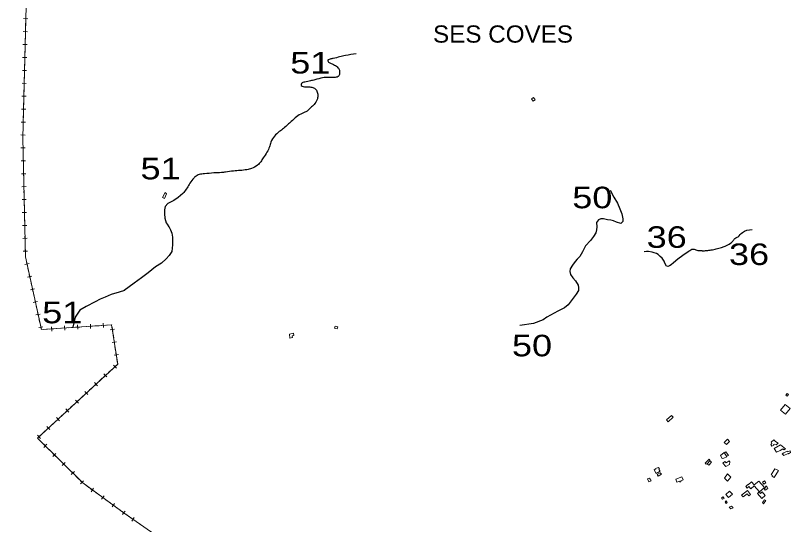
# Model space of a CAD drawing. Extents: x 476989 to 498418, y 4381813 to 4416555.
# Drawn here: x 483851 to 485648, y 4385368 to 4386550 of the extents above; entities that cross this region are included whole.
import ezdxf
from ezdxf.enums import TextEntityAlignment as Align

# ---------------------------------------------------------------- set-up
doc = ezdxf.new("R2010")
doc.units = 0
doc.header["$LTSCALE"] = 20
doc.linetypes.add('MEDIUM_DASHED', pattern=[4.5, 3, -1.5])
for name, color, linetype, lineweight in [('13', 7, 'Continuous', 13), ('34', 7, 'Continuous', 13), ('47', 7, 'Continuous', 13), ('48', 7, 'MEDIUM_DASHED', 13), ('6', 7, 'Continuous', 25)]:
    doc.layers.add(name, color=color, linetype=linetype, lineweight=lineweight)
doc.layers.add('7', color=7, linetype='Continuous')

msp = doc.modelspace()

# ---------------------------------------------------------------- linework, layer by layer
at = {"layer": '34'}
for p, q in [((483869.82, 4386542.81), (483879.82, 4386542.56)), ((483874.94, 4386547.69), (483874.7, 4386537.69)), ((483874.57, 4386532.69), (483874.33, 4386522.69)), ((483869.08, 4386512.82), (483879.08, 4386512.57)), ((483873.83, 4386502.7), (483873.59, 4386492.7)), ((483874.2, 4386517.7), (483873.96, 4386507.7)), ((483868.34, 4386482.83), (483878.34, 4386482.58)), ((483873.46, 4386487.7), (483873.22, 4386477.71)), ((483873.09, 4386472.71), (483872.85, 4386462.71)), ((483867.6, 4386452.84), (483877.6, 4386452.59)), ((483872.5, 4386448.65), (483872.48, 4386447.72)), ((483872.72, 4386457.71), (483872.5, 4386448.65)), ((483872.35, 4386442.72), (483872.11, 4386432.72)), ((483866.86, 4386422.85), (483876.86, 4386422.6)), ((483871.62, 4386412.73), (483871.37, 4386402.73)), ((483871.99, 4386427.72), (483871.74, 4386417.73)), ((483866.12, 4386392.86), (483876.12, 4386392.61)), ((483871.25, 4386397.73), (483871, 4386387.74)), ((483870.88, 4386382.74), (483870.63, 4386372.74)), ((483865.39, 4386362.87), (483875.38, 4386362.62)), ((483870.51, 4386367.74), (483870.26, 4386357.74)), ((483870.14, 4386352.75), (483869.89, 4386342.75)), ((483864.65, 4386332.88), (483874.64, 4386332.63)), ((483869.4, 4386322.75), (483869.15, 4386312.76)), ((483869.77, 4386337.75), (483869.52, 4386327.75)), ((483869.03, 4386307.76), (483868.78, 4386297.76)), ((483863.91, 4386302.88), (483873.9, 4386302.64)), ((483868.66, 4386292.76), (483868.41, 4386282.77)), ((483863.17, 4386272.89), (483873.17, 4386272.65)), ((483868.29, 4386277.77), (483868.04, 4386267.77)), ((483868.07, 4386262.77), (483868.29, 4386252.78)), ((483863.51, 4386242.67), (483873.5, 4386242.89)), ((483868.4, 4386247.78), (483868.61, 4386237.78)), ((483868.72, 4386232.78), (483868.94, 4386222.78)), ((483869.05, 4386217.78), (483869.27, 4386207.79)), ((483864.16, 4386212.68), (483874.16, 4386212.89)), ((483869.37, 4386202.79), (483869.59, 4386192.79)), ((483864.81, 4386182.68), (483874.81, 4386182.9)), ((483869.7, 4386187.79), (483869.92, 4386177.79)), ((483870.03, 4386172.79), (483870.24, 4386162.8)), ((483865.46, 4386152.69), (483875.46, 4386152.91)), ((483870.35, 4386157.8), (483870.57, 4386147.8)), ((483870.68, 4386142.8), (483870.9, 4386132.8)), ((483871, 4386127.8), (483871.22, 4386117.81)), ((483866.11, 4386122.7), (483876.11, 4386122.91)), ((483871.33, 4386112.81), (483871.55, 4386102.81)), ((483866.77, 4386092.7), (483876.76, 4386092.92)), ((483871.66, 4386097.81), (483871.87, 4386087.81)), ((483871.98, 4386082.82), (483872.2, 4386072.82)), ((483867.42, 4386062.71), (483877.42, 4386062.93)), ((483872.31, 4386067.82), (483872.53, 4386057.82)), ((483872.63, 4386052.82), (483872.85, 4386042.82)), ((483872.96, 4386037.83), (483873.18, 4386027.83)), ((483868.07, 4386032.72), (483878.07, 4386032.94)), ((483873.29, 4386022.83), (483873.5, 4386012.83)), ((483868.72, 4386002.73), (483878.72, 4386002.94)), ((483873.61, 4386007.83), (483873.83, 4385997.84)), ((483872.79, 4385972.17), (483882.55, 4385974.3)), ((483876.6, 4385978.12), (483878.74, 4385968.35)), ((483879.81, 4385963.47), (483881.95, 4385953.7)), ((483879.2, 4385942.86), (483888.97, 4385945)), ((483883.02, 4385948.81), (483885.16, 4385939.04)), ((483886.23, 4385934.16), (483888.36, 4385924.39)), ((483885.62, 4385913.55), (483895.39, 4385915.69)), ((483889.43, 4385919.51), (483891.57, 4385909.74)), ((483892.64, 4385904.85), (483894.78, 4385895.09)), ((483895.85, 4385890.2), (483897.99, 4385880.43)), ((483892.03, 4385884.25), (483901.8, 4385886.39)), ((483899.06, 4385875.55), (483901.2, 4385865.78)), ((483898.45, 4385854.94), (483908.22, 4385857.08)), ((483902.27, 4385860.9), (483904.4, 4385851.13)), ((483905.47, 4385846.24), (483907.61, 4385836.47)), ((484055.17, 4385825.72), (484054.5, 4385835.7)), ((483904.87, 4385825.64), (483914.64, 4385827.77)), ((483908.68, 4385831.59), (483910.82, 4385821.82)), ((483915.15, 4385821.28), (483925.13, 4385821.95)), ((483930.12, 4385822.29), (483940.09, 4385822.96)), ((483935.44, 4385817.64), (483934.77, 4385827.62)), ((483945.08, 4385823.3), (483955.06, 4385823.97)), ((483960.05, 4385824.31), (483970.03, 4385824.98)), ((483965.37, 4385819.66), (483964.7, 4385829.64)), ((483975.01, 4385825.32), (483984.99, 4385825.99)), ((483989.98, 4385826.33), (483999.96, 4385827)), ((483995.31, 4385821.68), (483994.63, 4385831.66)), ((484004.95, 4385827.34), (484014.92, 4385828.01)), ((484019.91, 4385828.35), (484029.89, 4385829.02)), ((484025.24, 4385823.7), (484024.56, 4385833.68)), ((484034.88, 4385829.36), (484044.86, 4385830.03)), ((484049.84, 4385830.37), (484059.82, 4385831.04)), ((484070.7, 4385820.58), (484080.58, 4385822.1)), ((484074.88, 4385826.28), (484076.4, 4385816.39)), ((484077.16, 4385811.45), (484078.68, 4385801.57)), ((484075.26, 4385790.93), (484085.14, 4385792.45)), ((484079.44, 4385796.63), (484080.96, 4385786.74)), ((484081.72, 4385781.8), (484083.24, 4385771.92)), ((484084, 4385766.98), (484085.52, 4385757.09)), ((484079.82, 4385761.27), (484089.71, 4385762.79)), ((484086.28, 4385752.15), (484087.81, 4385742.27)), ((484074.26, 4385728.29), (484066.92, 4385721.5)), ((484085.27, 4385738.48), (484077.93, 4385731.69)), ((484078.2, 4385738.75), (484084.99, 4385731.41)), ((484063.24, 4385718.11), (484055.9, 4385711.32)), ((484056.18, 4385718.38), (484062.97, 4385711.04)), ((484041.22, 4385697.74), (484033.88, 4385690.95)), ((484034.15, 4385698.02), (484040.94, 4385690.67)), ((484052.23, 4385707.92), (484044.89, 4385701.13)), ((484019.19, 4385677.37), (484011.85, 4385670.58)), ((484012.13, 4385677.65), (484018.92, 4385670.31)), ((484030.21, 4385687.56), (484022.86, 4385680.77)), ((483997.17, 4385657), (483989.82, 4385650.21)), ((483990.1, 4385657.28), (483996.89, 4385649.94)), ((484008.18, 4385667.19), (484000.84, 4385660.4)), ((483986.15, 4385646.82), (483978.81, 4385640.03)), ((483964.13, 4385626.45), (483956.79, 4385619.66)), ((483975.14, 4385636.64), (483967.8, 4385629.85)), ((483968.07, 4385636.91), (483974.86, 4385629.57)), ((483942.1, 4385606.08), (483934.76, 4385599.29)), ((483953.11, 4385616.27), (483945.77, 4385609.48)), ((483946.05, 4385616.54), (483952.84, 4385609.2)), ((483920.08, 4385585.71), (483912.73, 4385578.93)), ((483931.09, 4385595.9), (483923.75, 4385589.11)), ((483924.02, 4385596.18), (483930.81, 4385588.83)), ((483902, 4385575.81), (483908.79, 4385568.47)), ((483905.82, 4385565.21), (483912.93, 4385558.18)), ((483916.48, 4385554.66), (483923.58, 4385547.62)), ((483916.51, 4385547.59), (483923.55, 4385554.69)), ((483927.14, 4385544.1), (483934.24, 4385537.06)), ((483937.79, 4385533.55), (483944.9, 4385526.51)), ((483937.83, 4385526.48), (483944.87, 4385533.58)), ((483948.45, 4385522.99), (483955.56, 4385515.95)), ((483959.11, 4385512.43), (483966.21, 4385505.4)), ((483959.14, 4385505.36), (483966.18, 4385512.47)), ((483969.77, 4385501.88), (483976.87, 4385494.84)), ((483980.42, 4385491.32), (483987.53, 4385484.29)), ((483980.46, 4385484.25), (483987.49, 4385491.36)), ((483991.08, 4385480.77), (483998.19, 4385473.73)), ((484001.77, 4385463.14), (484008.81, 4385470.25)), ((484013.14, 4385460.53), (484021.22, 4385454.63)), ((484025.26, 4385451.69), (484033.34, 4385445.8)), ((484026.35, 4385444.7), (484032.24, 4385452.78)), ((484037.38, 4385442.85), (484045.46, 4385436.96)), ((484049.5, 4385434.01), (484057.58, 4385428.12)), ((484050.59, 4385427.03), (484056.48, 4385435.11)), ((484061.62, 4385425.18), (484069.7, 4385419.28)), ((484073.74, 4385416.34), (484081.82, 4385410.45)), ((484074.83, 4385409.35), (484080.72, 4385417.43)), ((484085.86, 4385407.5), (484093.94, 4385401.61)), ((484097.98, 4385398.66), (484103, 4385395)), ((484099.07, 4385391.68), (484103.23, 4385397.38)), ((484103.23, 4385397.38), (484104.96, 4385399.76)), ((484107.1, 4385392.14), (484115.31, 4385386.42)), ((484119.41, 4385383.57), (484127.61, 4385377.85)), ((484120.65, 4385376.61), (484126.37, 4385384.81)), ((484131.72, 4385374.99), (484139.92, 4385369.27))]:
    msp.add_line(p, q, dxfattribs=at)
for points in [[(484108, 4387807), (483853, 4387811), (483851, 4387468), (483887, 4387037), (483872.5, 4386448.65)], [(483872.5, 4386448.65), (483868, 4386266), (483874, 4385990), (483911, 4385821), (484074, 4385832), (484088, 4385741), (483902, 4385569), (484007, 4385465), (484103, 4385395), (484103.22, 4385394.84)], [(483873.94, 4385992.84), (483874, 4385990), (483875.53, 4385983)], [(484064.81, 4385831.38), (484074, 4385832), (484074.12, 4385831.22)], [(483909.06, 4385575.53), (483902, 4385569), (483902.27, 4385568.73)], [(484001.74, 4385470.21), (484007, 4385465), (484009.1, 4385463.47)], [(484103.22, 4385394.84), (484291, 4385264), (484102.72, 4385164.38)]]:
    msp.add_lwpolyline(points, dxfattribs=at)
at = {"layer": '47'}
for points in [[(485640.17, 4385672.6), (485643.66, 4385670.19), (485640.91, 4385666.22), (485637.42, 4385668.63)], [(485635.68, 4385647.23), (485647.33, 4385637.86), (485636.56, 4385624.48), (485624.91, 4385633.85)], [(485375.86, 4385617.36), (485364.42, 4385607.2), (485360.77, 4385611.28), (485372.16, 4385621.45)], [(485501.94, 4385566.31), (485494.71, 4385558.99), (485499.66, 4385554.11), (485506.89, 4385561.43)], [(485619.69, 4385557.64), (485613.67, 4385561.55), (485609.59, 4385565.06), (485603.44, 4385559.82), (485605.27, 4385556.65), (485602.46, 4385554.21), (485604.95, 4385550.05), (485609.94, 4385552.83), (485608.92, 4385554.42), (485611.48, 4385555.06), (485615.13, 4385553.2)], [(485625.19, 4385553.51), (485610.05, 4385544.72), (485615.41, 4385536.24), (485624.62, 4385540.46), (485630.23, 4385543.98), (485632.89, 4385541.54), (485636.84, 4385544.49)], [(485500.76, 4385525.8), (485493.57, 4385522.16), (485490.11, 4385521.53), (485485.71, 4385528.5), (485494.07, 4385535.43)], [(485647.5, 4385539.76), (485641.24, 4385537.45), (485640.36, 4385539.11), (485632.5, 4385534.95), (485628.57, 4385532.83), (485632.55, 4385528.34), (485642.83, 4385533.52), (485643.57, 4385532.76), (485648.26, 4385535.32)], [(485461.45, 4385516.54), (485454.91, 4385509.66), (485458.68, 4385506.07), (485465.22, 4385512.95)], [(485491.39, 4385511.08), (485498.17, 4385502.8), (485506.43, 4385508.01), (485507.49, 4385514.15), (485506.17, 4385515.97), (485499.43, 4385512.02), (485496.02, 4385514.62)], [(485336.5, 4385486.96), (485331.77, 4385495.38), (485335.76, 4385497.44), (485335.29, 4385498.25), (485342.2, 4385500.73), (485344.58, 4385496.66), (485343.21, 4385496.15), (485345.76, 4385492.09)], [(485620.73, 4385493.69), (485610.59, 4385477.56), (485605.81, 4385480.55), (485606.79, 4385482.13), (485603.55, 4385484.13), (485612.08, 4385497.96)], [(485346.38, 4385488.49), (485348.86, 4385485.12), (485341.52, 4385480.52), (485338.96, 4385484.25)], [(485382.2, 4385473.84), (485385, 4385466.76), (485390.55, 4385468.79), (485391.34, 4385466.68), (485394.27, 4385468.09), (485393.65, 4385469.76), (485399.3, 4385472.35), (485396.43, 4385479.26)], [(485501.99, 4385486.17), (485494.94, 4385476.06), (485501.89, 4385468.84), (485509.91, 4385478.63)], [(485316.66, 4385474.25), (485319.79, 4385467.3), (485324.91, 4385469.72), (485321.65, 4385475.92)], [(485576.12, 4385444.28), (485564.24, 4385457.89), (485556.57, 4385451.2), (485551.89, 4385456.56), (485547.94, 4385453.11), (485544.46, 4385457.09), (485549.66, 4385461.64), (485550.29, 4385460.91), (485558.02, 4385467.59), (485564.31, 4385460.3), (485574.72, 4385469.29), (485587.69, 4385454.27)], [(485583.19, 4385466.47), (485586.58, 4385462.08), (485591.06, 4385465.53), (485587.67, 4385469.92)], [(485513.39, 4385438.88), (485504.37, 4385430.87), (485498, 4385438.05), (485507.02, 4385446.06)], [(485534.82, 4385436.85), (485548.41, 4385447.53), (485555.55, 4385438.42), (485551.49, 4385435.24), (485547.76, 4385439.99), (485538.35, 4385432.6)], [(485571.57, 4385440.75), (485581.68, 4385428.75), (485589.75, 4385435.55), (485582.63, 4385443.99), (485578.45, 4385440.47), (485575.5, 4385443.96)], [(485591.25, 4385458.17), (485589.16, 4385453.18), (485586.96, 4385451.48), (485589.53, 4385448.14), (485595.75, 4385452.26), (485594.06, 4385455.21)], [(485488.51, 4385430.38), (485490.9, 4385426.94), (485494.12, 4385429.18), (485491.73, 4385432.62)], [(485496.41, 4385421.49), (485499.18, 4385417.58), (485501.63, 4385419.31), (485498.86, 4385423.22)], [(485587.94, 4385426.11), (485583.51, 4385419.27), (485585.96, 4385416.4), (485590.99, 4385424.11)], [(485515.18, 4385406.96), (485509.98, 4385405.16), (485506.28, 4385408.67), (485511.49, 4385410.99)]]:
    msp.add_lwpolyline(points, close=True, dxfattribs=at)
at = {"layer": '48'}
for points in [[(485047.97, 4386357.07), (485051.39, 4386351.42), (485055.76, 4386354.03), (485052.03, 4386360.03)], [(484201.31, 4386136.21), (484196.74, 4386125.7), (484192.21, 4386127.89), (484197.76, 4386139.26)], [(484598.89, 4385827.25), (484597.24, 4385822.7), (484590.88, 4385824.37), (484592.65, 4385829.02)], [(484495.64, 4385812.34), (484486.27, 4385810.61), (484487.44, 4385801.36), (484493.55, 4385802.32), (484492.91, 4385806.73), (484496.44, 4385807.23)]]:
    msp.add_lwpolyline(points, close=True, dxfattribs=at)
for points in [[(485494.62, 4385534.65), (485498.59, 4385537.17), (485504.3, 4385529.07), (485499.88, 4385527.08)], [(485462.03, 4385516), (485459.32, 4385519.8), (485450.49, 4385510.99), (485453.01, 4385508.33), (485455.17, 4385509.42)]]:
    msp.add_lwpolyline(points, dxfattribs=at)
at = {"layer": '6'}
for points in [[(485230.17, 4386144.48), (485238.93, 4386128.18), (485246.9, 4386114.26), (485252.47, 4386101.54), (485256.85, 4386090.01), (485259.24, 4386078.08), (485259.64, 4386072.11), (485254.86, 4386067.34), (485244.91, 4386070.52), (485238.14, 4386073.31), (485231.37, 4386075.3), (485224.2, 4386075.69), (485214.64, 4386078.48), (485208.67, 4386078.08), (485202.69, 4386075.69), (485198.31, 4386069.33), (485199.11, 4386059.57), (485198.71, 4386052.8), (485197.12, 4386045.64), (485191.54, 4386036.89), (485184.77, 4386028.13), (485173.22, 4386015.8), (485165.66, 4386001.18), (485159.68, 4385990.84), (485153.71, 4385984.47), (485148.53, 4385978.9), (485142.56, 4385970.54), (485137.38, 4385962.19), (485136.19, 4385955.82), (485138.18, 4385948.66), (485143.75, 4385941.1), (485149.33, 4385933.93), (485155.7, 4385924.38), (485156.89, 4385919), (485156.89, 4385911.43), (485150.92, 4385903.48), (485133, 4385878.41), (485124.24, 4385871.64), (485108.82, 4385863.4), (485083.33, 4385849.87), (485074.57, 4385843.9), (485052.27, 4385835.14), (485020.41, 4385830.77)], [(484239.1, 4386136.78), (484227.91, 4386127.44), (484218.03, 4386120.66), (484204.44, 4386113.88), (484198.27, 4386107.09), (484196.42, 4386099.08), (484196.42, 4386089.83), (484197.65, 4386079.35), (484200.74, 4386068.86), (484202.69, 4386065.47), (484206.59, 4386059.6)], [(484206.44, 4386060.05), (484210.6, 4386052.54), (484213.69, 4386045.14), (484214.93, 4386035.26), (484214.93, 4386025.39), (484214.93, 4386017.37), (484213.69, 4386002.56), (484207.51, 4385993.3), (484200.72, 4385985.28), (484189.6, 4385975.41), (484176.02, 4385966.77), (484158.73, 4385952.57), (484143.29, 4385941.47), (484125.99, 4385928.51), (484103.14, 4385911.85)], [(485360.44, 4385967.89), (485357.02, 4385975.21), (485355.18, 4385980.08), (485350.75, 4385986.5), (485345.66, 4385990.53), (485341.11, 4385995.13), (485337.24, 4385997.82), (485332.38, 4385999.2), (485327.57, 4386000.86), (485318.71, 4386002.15), (485313.97, 4386002.06), (485308.63, 4386001.53)], [(485410.77, 4386001.69), (485398.53, 4385992.68), (485387.19, 4385984.33), (485376.75, 4385975.81), (485371.33, 4385971.08), (485367.37, 4385968.65), (485364.11, 4385967.7), (485360.44, 4385967.89)], [(484103.55, 4385911.73), (484091.43, 4385907.86), (484072.53, 4385902.53), (484058.95, 4385896.24), (484047.32, 4385891.4), (484035.69, 4385885.59), (484014.85, 4385874.95), (484000.3, 4385866.24), (483989.64, 4385849.78), (483983.82, 4385826.55)]]:
    msp.add_lwpolyline(points, dxfattribs=at)
for points in [[(484576.61, 4386447.19), (484575.13, 4386446.53), (484575.18, 4386444.85), (484580.13, 4386440.31), (484591.1, 4386435.01), (484598.73, 4386428.86), (484602.1, 4386423.08), (484602.37, 4386415.22), (484599.42, 4386408.45), (484594.78, 4386406.63), (484585.36, 4386406.05), (484576.72, 4386406.48), (484563.21, 4386405.29), (484545.28, 4386400.82), (484534.96, 4386398.38), (484521.91, 4386395.52), (484514.17, 4386392.31), (484513.85, 4386387.73), (484523.95, 4386384.82), (484528.86, 4386384.69), (484538.58, 4386383.69), (484545.75, 4386380.25), (484548.92, 4386376.43), (484552.06, 4386367.9), (484551.7, 4386358.89), (484550.52, 4386355.02), (484543.31, 4386343.35), (484535.9, 4386336.43), (484527.04, 4386328.4), (484515.84, 4386322.97), (484502.88, 4386315.06), (484490.08, 4386303.77), (484482.61, 4386296.93), (484472.42, 4386287.91), (484462.75, 4386280.64), (484451.72, 4386270.36), (484442.91, 4386255.77), (484439.95, 4386245.25), (484434.08, 4386232.96), (484425.31, 4386219.46), (484419.84, 4386210.8), (484412.03, 4386202.36), (484398.36, 4386194.84), (484387.5, 4386192.19), (484372.49, 4386190.28), (484356.35, 4386188.98), (484338.03, 4386186.55), (484328.45, 4386185.35), (484310.94, 4386184.71), (484289, 4386182.56), (484276.75, 4386181.11), (484267.68, 4386175.87), (484262.62, 4386170.12), (484253.51, 4386158.01), (484247.07, 4386147.03), (484239.03, 4386136.69)], [(484641.08, 4386461.3), (484615.93, 4386456.98), (484602.56, 4386454.05), (484588.02, 4386450.63), (484580.56, 4386448.95), (484576.61, 4386447.19)], [(485443.74, 4386004.16), (485443.83, 4386004.15), (485453.51, 4386004.46), (485464.41, 4386005.81), (485476.23, 4386008.42), (485488.14, 4386011.85), (485496.43, 4386014.96), (485508.98, 4386021.45), (485513.76, 4386025.14), (485517.53, 4386031.09), (485526.61, 4386036.58), (485536.73, 4386046.57), (485559.1, 4386053.59)], [(485443.74, 4386004.16), (485434.22, 4386003.76), (485425.36, 4386006.76), (485422.62, 4386007.16), (485419.49, 4386006.67), (485415.18, 4386003.87), (485410.89, 4386001.79)]]:
    msp.add_spline(points, degree=3, dxfattribs=at)

# ---------------------------------------------------------------- texts
at = {"layer": '13', "width": 1.25}
for s, p in [('51', (484534.7, 4386415.46)), ('51', (484187.42, 4386169.73)), ('50', (485188.67, 4386102.67)), ('36', (485361.09, 4386010.77)), ('36', (485552.18, 4385970.88)), ('51', (483959.38, 4385835.64)), ('50', (485048.84, 4385758.93))]:
    msp.add_text(s, height=50, dxfattribs=at).set_placement(p, align=Align.CENTER)
at = {"layer": '7', "width": 1.05}
msp.add_text('SES COVES', height=40, dxfattribs=at).set_placement((484981.57, 4386487.15), align=Align.CENTER)

doc.saveas('drawing.dxf')
